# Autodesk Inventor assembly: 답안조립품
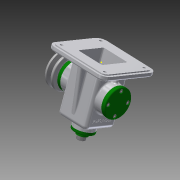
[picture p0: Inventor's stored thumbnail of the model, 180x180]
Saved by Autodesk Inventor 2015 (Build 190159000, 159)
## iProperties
Created: 2016-02
Part Number: 답안조립품
Document SubType Name: Assembly
Designer: Administrator
Author: Administrator
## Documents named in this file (19)
- C:\Users\Administrator\Desktop\460219V1008\답안조립품.iam
- C:\Users\Administrator\Desktop\460219V1008\V-벨트풀리.ipt
- C:\Users\Administrator\Desktop\460219V1008\고정핀.ipt
- C:\Users\Administrator\Desktop\460219V1008\뒤커버.ipt
- C:\Users\Administrator\Desktop\460219V1008\링크.ipt
- C:\Users\Administrator\Desktop\460219V1008\멈춤링 6 x 5.ipt
- C:\Users\Administrator\Desktop\460219V1008\멈춤링 15 x 1.ipt
- C:\Users\Administrator\Desktop\460219V1008\베어링 15 x 35 x 11.ipt
- C:\Users\Administrator\Desktop\460219V1008\본체.ipt
- C:\Users\Administrator\Desktop\460219V1008\볼트 M3 x 8.ipt
- C:\Users\Administrator\Desktop\460219V1008\볼트 M4 x 10.ipt
- C:\Users\Administrator\Desktop\460219V1008\볼트 M6 x 12.ipt
- C:\Users\Administrator\Desktop\460219V1008\상부부시.ipt
- C:\Users\Administrator\Desktop\460219V1008\슬라이드바.ipt
- C:\Users\Administrator\Desktop\460219V1008\앞커버.ipt
- C:\Users\Administrator\Desktop\460219V1008\오일실 15 25 7.ipt
- C:\Users\Administrator\Desktop\460219V1008\와셔.ipt
- C:\Users\Administrator\Desktop\460219V1008\키 5 x 5 x 14.ipt
- C:\Users\Administrator\Desktop\460219V1008\편심축.ipt
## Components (15 placed, 5 different names)
1. V-벨트풀리:1
2. 고정핀:1
3. ISO 4018 M6 x 12:1
4. ISO 4762 M3 x 8:1
5. ISO 4762 M3 x 8:2
6. ISO 4762 M3 x 8:3
7. ISO 4762 M3 x 8:4
8. ISO 4762 M4 x 10:1
9. ISO 4762 M4 x 10:3
10. ISO 4762 M4 x 10:4
11. ISO 4762 M4 x 10:5
12. ISO 4762 M4 x 10:2
13. ISO 4762 M4 x 10:6
14. ISO 4762 M4 x 10:7
15. ISO 4762 M4 x 10:8
